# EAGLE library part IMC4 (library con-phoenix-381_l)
Invertierter Mini-Combicon 3.81mm horizontal 4-polig IMC 1,5/4-G-3,81 (ohne Gegenstecker)
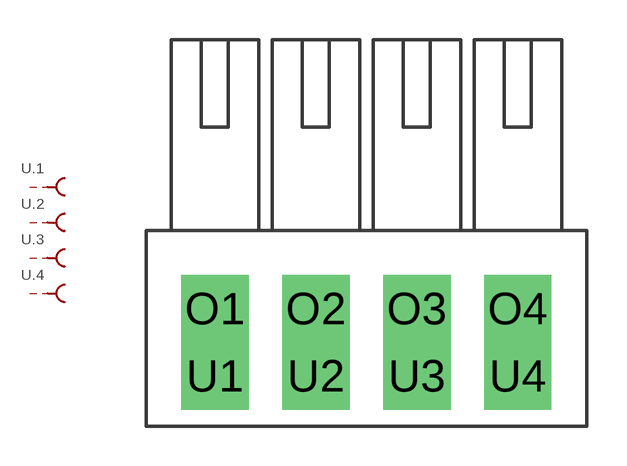
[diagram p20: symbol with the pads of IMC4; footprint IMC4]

Designator prefix -; gates .1=MCBU .2=MCBU .3=MCBU .4=MCBU

## IMC4  [IMC4]
O1  .1:S  pas
O2  .2:S  pas
O3  .3:S  pas
O4  .4:S  pas
U1  .1:SK  pas
U2  .2:SK  pas
U3  .3:SK  pas
U4  .4:SK  pas

## Footprint IMC4 (pad centres in mm)
Mini-Combicon 3.81mm horizontal 4-polig invertiert (ohne Gegenstecker)
drill 1.3 pad 2.54 square: O1 -5.715,1.27; O2 -1.905,1.27; O3 1.905,1.27; O4 5.715,1.27; U1 -5.715,-1.27; U2 -1.905,-1.27; U3 1.905,-1.27; U4 5.715,-1.27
